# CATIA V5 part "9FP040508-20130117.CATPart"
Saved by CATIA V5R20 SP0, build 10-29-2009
Part number: 9FP040508-20130117
Revision: ANY
Definition: UNKNOWN
Nomenclature: 9FP040508-20130117
Source: Unknown
Bounding box of the stored display mesh (mm): x -4 to 4, y -4 to 4, z 0 to 6
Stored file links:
  C:\Users\Utente\Desktop\IO LAVORO\3D X SITO CF\CUMSA\3D files PF\PF 054150\9FP040508-20130117.CATPart
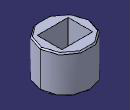
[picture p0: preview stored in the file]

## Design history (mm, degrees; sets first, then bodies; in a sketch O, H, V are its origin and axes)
Body1 "Chaflán1" (main body)
  Solid1: solid without history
